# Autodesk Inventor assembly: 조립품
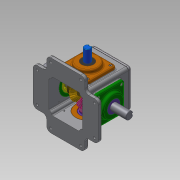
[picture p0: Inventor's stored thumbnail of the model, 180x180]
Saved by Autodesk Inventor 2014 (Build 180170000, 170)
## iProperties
Created: 2019-12
Part Number: 조립품
Document SubType Name: Assembly
Designer: net
Mass: 4194.66 g
Surface Area: 3365.09 cm^2
Volume: 1062.39 cm^3
Density: 3.94833 g/cm^3
Author: net
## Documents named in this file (16)
- C:\Users\net\Desktop\391204V1064\조립품.iam
- C:\Users\net\Desktop\391204V1064\본체.ipt
- C:\Users\net\Desktop\391204V1064\개스킷.ipt
- C:\Users\net\Desktop\391204V1064\메인베벨기어.ipt
- C:\Users\net\Desktop\391204V1064\메인축.ipt
- C:\Users\net\Desktop\391204V1064\메인커버.ipt
- C:\Users\net\Desktop\391204V1064\베어링 6203.ipt
- C:\Users\net\Desktop\391204V1064\베어링 6204.ipt
- C:\Users\net\Desktop\391204V1064\볼트 M4.ipt
- C:\Users\net\Desktop\391204V1064\상부커버.ipt
- C:\Users\net\Desktop\391204V1064\서브베벨기어.ipt
- C:\Users\net\Desktop\391204V1064\서브축.ipt
- C:\Users\net\Desktop\391204V1064\서브커버.ipt
- C:\Users\net\Desktop\391204V1064\오일 실 17 32 8.ipt
- C:\Users\net\Desktop\391204V1064\오일 실 20 35 8.ipt
- C:\Users\net\Desktop\391204V1064\키 4x4.ipt
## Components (1 placed, 1 different names)
1. 개스킷:1
